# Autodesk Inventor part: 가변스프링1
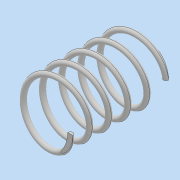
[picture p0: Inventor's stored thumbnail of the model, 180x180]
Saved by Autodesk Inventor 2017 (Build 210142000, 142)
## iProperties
Part Number: 가변스프링1
Material: 일반
Document SubType Name: Modeling
Designer: MRC
Density: 1 g/cm^3
Appearance: 기본값
Author: MRC
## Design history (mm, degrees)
sketch "스케치1"
  geometry: L1 (0, 0)-(11, 0); L2 (11, 0)-(11, 37.411); L3 (11, 37.411)-(0, 37.411); L4 (0, 37.411)-(0, 0); C1 r 1 at (11, 0)
  constraints: 8 end point, 2 parallel, 1 centre point, 1 coincident, 1 horizontal, 1 perpendicular
  dimensions: "d0" = 22 diameter of L2 L4; "d1" = 2 diameter of C1; "d2" = 37.4112 distance between parallel lines of L1 L3 (derived)
feature "코일1" sketch "스케치1" pitch "d3" = 10; turns "d5" = 5; dims "d4" = 37.4112 (= d2), "d6" = 0, angle "d7" = 90 deg, angle "d8" = 90 deg, "d9" = 0, "d10" = 0
sketch "스케치2"
  geometry: L1 (-25.076, 37.411)-(25.076, 37.411); L2 (25.076, 37.411)-(25.076, 0); L3 (25.076, 0)-(-25.076, 0); L4 (-25.076, 0)-(-25.076, 37.411); L5 (0, 37.411)-(0, 0) reference; 2 further points
  constraints: 8 end point, 2 midpoint, 2 parallel, 1 coincident, 1 horizontal, 1 perpendicular
  dimensions: "d11" = 50.15108 distance of L1.start L1.end
extrude "돌출1" sketch "스케치2" stored distance "d12" = 0; taper "d13" = 0 deg
node "솔리드1"
